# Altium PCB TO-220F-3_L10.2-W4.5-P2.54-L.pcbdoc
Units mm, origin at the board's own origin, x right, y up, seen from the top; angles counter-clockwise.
Board outline 22.96 x 18.05 mm, 2 copper layers (Top Layer, Bottom Layer), stack 0 mm thick; 1 components, 0 nets, 3 pads, 0 vias.
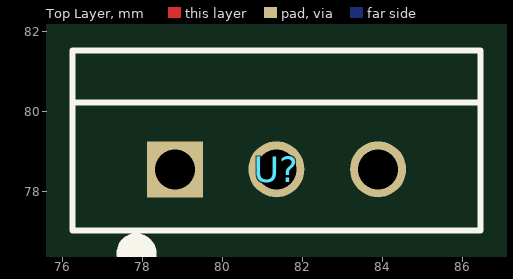
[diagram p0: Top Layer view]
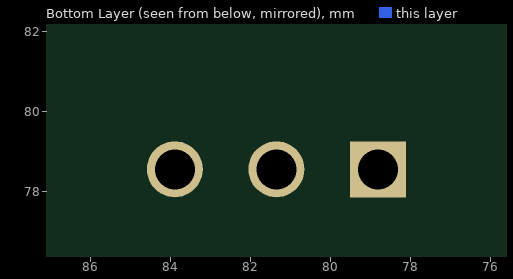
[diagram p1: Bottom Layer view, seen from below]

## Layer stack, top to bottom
Top Layer: signal copper (thickness not stored)
Bottom Layer: signal copper (thickness not stored)

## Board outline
92.81,69.85 69.85,69.85 69.85,87.899 92.81,87.899

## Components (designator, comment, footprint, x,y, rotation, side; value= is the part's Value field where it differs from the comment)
U? "" TO-220F-3_L10.2-W4.5-P2.54-L 81.36,78.55 r0 top

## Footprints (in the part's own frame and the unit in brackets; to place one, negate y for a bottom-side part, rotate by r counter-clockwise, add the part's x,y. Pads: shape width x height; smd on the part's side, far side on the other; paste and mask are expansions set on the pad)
TO-220F-3_L10.2-W4.5-P2.54-L [mm]
  rect 1.4x1.4 hole 1 paste+0 mask+0.05: 1(-2.54,0)
  round 1.4 hole 1 paste+0 mask+0.05: 2(0,0) 3(2.54,0)
  silkscreen extent -5.1,-2.35 5.1,2.97

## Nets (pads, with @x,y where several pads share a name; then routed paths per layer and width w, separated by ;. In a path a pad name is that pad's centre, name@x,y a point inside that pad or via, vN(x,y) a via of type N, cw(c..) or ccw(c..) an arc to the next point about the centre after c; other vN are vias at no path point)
pads on no net: U?.1 U?.2 U?.3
